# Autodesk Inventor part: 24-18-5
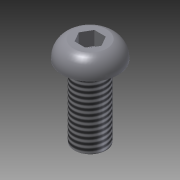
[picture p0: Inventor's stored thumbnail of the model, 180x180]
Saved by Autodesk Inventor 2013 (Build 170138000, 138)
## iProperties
Created: 2004-10
Part Number: 24-18-5
Material: Stahl (hohe Festigk., niedr. Legier.)
Document SubType Name: Modeling
Designer: Autodesk, Inc.
Manufacturer: Standard
Standards Organization: Custom
Description: SCREW, PARKER IPS, BUTTON HEAD, M5X8
Catalog Web Link: http://www.parker.com/ead/cm1.asp?cmid=809
Vendor: PARKER IPS
Mass: 10.8823 g
Surface Area: 9.37524 cm^2
Volume: 1.38805 cm^3
Density: 7.84 g/cm^3
CAGE: 1LJX3
Dept. ID: Product Design
Description #2: ---
Finish #1: ---
Finish #2: ---
Material ID: ---
Project Number: ---
Author: Autodesk, Inc.
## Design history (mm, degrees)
derived "2X-YYY-ZZ IPS Screws.ipt"
body "Solid1"
tag "TaggingFeature2"
feature "Solid1::2X-YYY-ZZ IPS Screws.ipt" dims "ScaleForDerivedMember" = 10
